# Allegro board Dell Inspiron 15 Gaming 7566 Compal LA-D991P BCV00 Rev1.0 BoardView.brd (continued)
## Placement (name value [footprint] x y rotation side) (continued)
PR810  0_0402_5%  [R0402_0OHM]  223.45 40.33 270 bottom
PR900  10K_0402_5%  [R_0402]  144.36 110.99 180 bottom
PR901  2.2_0603_5%  [R_0603]  143.37 114.53 90 bottom
PR902  30.1K_0402_1%  [R_0402]  144.36 110.1 180 bottom
PR903  0_0402_5%  [R0402_0OHM]  141.95 109.08 180 bottom
PR904  4.7_1206_5%  [R_1206]  144.35 124.32 180 top
PR905  470K_0402_1%  [R_0402]  138.06 110.91 90 bottom
PR906  9.31K_0402_1%  [R_0402]  140.17 109.08 180 bottom
PR907  10K_0402_1%  [R_0402]  140.17 110.1 180 bottom
PR908  0_0402_5%  [R0402_0OHM]  146.77 110.99 180 bottom
PR1000  0_0402_5%  [R0402_0OHM]  178.83 59.88 270 bottom
PR1001  10K_0402_1%  [R_0402]  177.81 59.88 270 bottom
PR1002  19.6K_0402_1%  [R_0402]  179.92 55.69 90 top
PR1003  2.2_0603_5%  [R_0603]  174 58.98 90 bottom
PR1004  2K_0402_1%  [R_0402]  180.81 57.52 180 top
PR1005  20K_0402_1%  [R_0402]  179.71 59.88 270 bottom
PR1006  18.2K_0402_1%  [R_0402]  180.81 58.41 180 top
PR1007  47K_0402_1%  [R_0402]  175.14 58.97 90 bottom
PR1008  47K_0402_1%  [R_0402]  176.92 58.97 90 bottom
PR1009  10_1206_5%  [R_1206]  165.62 57.08 270 top
PR1010  20_0402_1%  [R_0402]  180.73 54.55 270 top
PR1011  510K_0402_1%  [R_0402]  179.84 53.63 90 top
PR1012  0_0402_5%  [R0402_0OHM]  180.93 54.47 180 bottom
PR1013  100_0402_1%  [R_0402]  181.82 53.53 180 bottom
PR1014  13.3K_0402_1%  [R_0402]  171 55.49 0 bottom
PR1015  2.2_0603_5%  [R_0603]  174.38 51.36 270 bottom
PR1016  2.2_0603_5%  [R_0603]  171.84 53.65 270 bottom
PR1017  0_0402_5%  [R0402_0OHM]  181.82 52.64 180 bottom
PR1019  100_0402_1%  [R_0402]  181.82 51.76 180 bottom
PR1021  10K_0402_1%  [R_0402]  177.94 54.49 270 top
PR1022  10_1206_5%  [R_1206]  146.89 58.03 180 top
PR1023  10K_0402_1%  [R_0402]  178.95 53.13 90 top
PR1024  10K_0402_1%  [R_0402]  179.59 49.95 90 bottom
PR1026  1_0402_5%  [R_0402]  175.9 50.61 270 bottom
PR1027  10K_0402_1%  [R_0402]  178.19 49.95 90 bottom
PR1028  2.2_0603_5%  [R_0603]  177.05 51.11 270 bottom
PR1029  0_0402_5%  [R0402_0OHM]  200.19 58.03 0 top
PR1030  2.2_0603_5%  [R_0603]  207.49 58.36 180 top
PR1031  2.2_0603_5%  [R_0603]  201.09 55.24 180 top
PR1032  10_1206_5%  [R_1206]  189.18 70.48 0 top
PR1100  12.1K_0402_1%  [R_0402]  65.54 83.1 90 bottom
PR1101  1_0402_5%  [R_0402]  72.78 80.64 90 bottom
PR1102  0_0402_5%  [R0402_0OHM]  73.67 80.69 90 bottom
PR1103  45.3_0402_1%  [R_0402]  69.57 80.67 90 bottom
PR1104  100_0402_1%  [R_0402]  70.88 80.69 90 bottom
PR1105  97.6K_0402_1%  [R_0402]  64.78 85 90 bottom
PR1106  10_0402_1%  [R_0402]  70.88 83.1 90 bottom
PR1107  0_0402_5%  [R0402_0OHM]  69.99 83.1 90 bottom
PR1108  49.9_0402_1%  [R_0402]  69.1 83.1 90 bottom
PR1109  100_0402_1%  [R_0402]  68.46 83.1 90 top
PR1110  27.4K_0402_1%  [R_0402]  65.73 85.03 270 top
PR1111  10.2K_0402_1%  [R_0402]  66.62 84.11 90 top
PR1112  1.91K_0402_1%  [R_0402]  68.21 83.1 90 bottom
PR1113  165K_0402_1%  [R_0402]  76.51 85.33 0 bottom
PR1114  16.9K_0402_1%  [R_0402]  76.72 84.14 270 bottom
PR1115  5.62K_0402_1%  [R_0402]  75.83 84.14 270 bottom
PR1116  110K_0402_1%  [R_0402]  74.94 84.14 270 bottom
PR1117  0_0402_5%  [R0402_0OHM]  67.57 83.1 90 top
PR1118  3.6K_0402_1%  [R_0402]  65.72 87.75 0 top
PR1119  2K_0402_1%  [R_0402]  65.72 88.76 0 bottom
PR1120  0_0402_5%  [R0402_0OHM]  67.32 83.1 90 bottom
PR1121  1.1K_0402_1%  [R_0402]  76.51 88 0 bottom
PR1122  1K_0402_1%  [R_0402]  66.56 86.91 90 bottom
PR1123  48.7K_0402_1%  [R_0402]  76.51 86.22 0 bottom
PR1124  1K_0402_1%  [R_0402]  78.37 87.1 90 bottom
PR1125  2.61K_0402_1%  [R_0402]  129.17 118.1 180 bottom
PR1126  11K_0402_1%  [R_0402]  79.44 86.35 0 bottom
PR1127  2.94K_0402_1%  [R_0402]  64.7 87.81 0 bottom
PR1128  1K_0402_1%  [R_0402]  80.72 91.1 90 bottom
PR1129  2.67K_0402_1%  [R_0402]  80.71 90.16 0 bottom
PR1130  2.61K_0402_1%  [R_0402]  86.88 121.35 270 bottom
PR1131  11K_0402_1%  [R_0402]  63.43 91.43 0 bottom
PR1132  1K_0402_1%  [R_0402]  65.73 90.49 270 top
PR1133  4.42K_0402_1%  [R_0402]  78.55 92.57 0 bottom
PR1134  2K_0402_1%  [R_0402]  76.77 90.67 0 bottom
PR1135  115K_0402_1%  [R_0402]  77.61 91.73 90 bottom
PR1136  432_0402_1%  [R_0402]  66.62 90.49 270 top
PR1137  374_0402_1%  [R_0402]  76.6 95.75 180 bottom
PR1138  11K_0402_1%  [R_0402]  74.81 96.69 90 bottom
PR1139  1K_0402_1%  [R_0402]  76.34 97.6 270 bottom
PR1140  2.61K_0402_1%  [R_0402]  118.88 114.49 270 bottom
PR1141  10.2K_0402_1%  [R_0402]  68.84 95.7 270 bottom
PR1142  1K_0402_1%  [R_0402]  70.62 96.94 90 top
PR1143  90.9K_0402_1%  [R_0402]  67.07 94.78 90 bottom
PR1144  27.4K_0402_1%  [R_0402]  68.84 96.69 90 bottom
PR1145  2K_0402_1%  [R_0402]  70.62 94.78 90 bottom
PR1146  2.43K_0402_1%  [R_0402]  70.61 95.62 0 top
PR1147  4.87K_0402_1%  [R_0402]  69.73 94.78 90 bottom
PR1400  1_0402_5%  [R_0402]  121.04 129.48 270 top
PR1401  0_0402_5%  [R0402_0OHM]  121.42 132.02 270 bottom
PR1402  1_0402_5%  [R_0402]  123.2 132.02 270 bottom
PR1403  10K_0402_1%  [R_0402]  120.98 129.73 270 bottom
PR1404  0_0402_5%  [R0402_0OHM]  122.31 132.02 270 bottom
PR1405  4.7_0603_1%  [R_0603]  126.5 132.26 270 bottom
PR1406  10_1206_5%  [R_1206]  124.7 121.25 0 top
PR1407  0_0402_5%  [R0402_0OHM-NPM]  123.77 120.14 270 bottom
PR1408  0_0402_5%  [R0402_0OHM-NPM]  123.77 115.93 90 bottom
PR1409  100K_0402_1%  [R_0402]  79.21 101.21 180 bottom
PR1410  3.65K_0603_1%  [R_0603]  79.7 102.35 180 bottom
PR1411  2.2_0402_1%  [R_0402]  75.65 102.1 180 bottom
PR1412  100K_0402_1%  [R_0402]  74.74 101.08 0 bottom
PR1413  100K_0402_1%  [R_0402]  75.65 100.07 180 bottom
PR1414  1_0402_5%  [R_0402]  110.88 129.73 270 top
PR1415  0_0402_5%  [R0402_0OHM]  111.01 132.02 270 bottom
PR1416  1_0402_5%  [R_0402]  112.79 132.02 270 bottom
PR1417  0_0402_5%  [R0402_0OHM]  111.9 132.02 270 bottom
PR1418  10K_0402_1%  [R_0402]  110.82 129.73 270 bottom
PR1419  4.7_0603_1%  [R_0603]  116.09 132.26 270 bottom
PR1420  10_1206_5%  [R_1206]  113.99 121.28 0 top
PR1421  0_0402_5%  [R0402_0OHM-NPM]  114.88 120.21 270 bottom
PR1422  0_0402_5%  [R0402_0OHM-NPM]  114.88 115.99 90 bottom
PR1423  100K_0402_1%  [R_0402]  77.23 103.06 270 bottom
PR1424  3.65K_0603_1%  [R_0603]  77.04 104.26 180 bottom
PR1425  2.2_0402_1%  [R_0402]  73.37 102.1 180 bottom
PR1426  100K_0402_1%  [R_0402]  73.37 101.08 180 bottom
PR1427  100K_0402_1%  [R_0402]  73.37 100.07 180 bottom
PR1428  1_0402_5%  [R_0402]  100.97 129.61 270 top
PR1429  0_0402_5%  [R0402_0OHM]  101.36 131.89 270 bottom
PR1430  1_0402_5%  [R_0402]  103.13 131.89 270 bottom
PR1431  0_0402_5%  [R0402_0OHM]  102.24 131.89 270 bottom
PR1432  10K_0402_1%  [R_0402]  100.91 129.61 270 bottom
PR1433  4.7_0603_1%  [R_0603]  106.44 132.13 270 bottom
PR1434  10_1206_5%  [R_1206]  104.09 121.15 0 top
PR1435  0_0402_5%  [R0402_0OHM-NPM]  105.23 119.98 270 bottom
PR1436  0_0402_5%  [R0402_0OHM-NPM]  105.23 115.89 90 bottom
PR1437  100K_0402_1%  [R_0402]  72.45 104.38 0 bottom
PR1438  3.65K_0603_1%  [R_0603]  74.11 106.04 0 bottom
PR1439  2.2_0402_1%  [R_0402]  70.95 102.1 180 bottom
PR1440  100K_0402_1%  [R_0402]  70.95 100.07 180 bottom
PR1441  100K_0402_1%  [R_0402]  70.95 101.08 180 bottom
PR1500  1_0402_5%  [R_0402]  90.69 129.61 270 top
PR1501  0_0402_5%  [R0402_0OHM]  91.07 131.89 270 bottom
PR1502  1_0402_5%  [R_0402]  92.85 131.89 270 bottom
PR1503  0_0402_5%  [R0402_0OHM]  91.96 131.89 270 bottom
PR1504  10K_0402_1%  [R_0402]  90.75 129.61 270 bottom
PR1505  4.7_0603_1%  [R_0603]  96.15 132.13 270 bottom
PR1506  0_0402_5%  [R0402_0OHM-NPM]  91.83 120.08 270 bottom
PR1507  0_0402_5%  [R0402_0OHM-NPM]  91.83 115.86 90 bottom
PR1508  4.7_1206_5%  [R_1206]  93.75 121.12 0 top
PR1509  3.65K_0603_1%  [R_0603]  65.35 102.23 180 bottom
PR1510  100K_0402_1%  [R_0402]  64.86 101.08 180 bottom
PR1511  2.2_0402_1%  [R_0402]  65.87 103.37 180 bottom
PR1512  1_0402_5%  [R_0402]  71.51 106.97 90 bottom
PR1513  0_0402_5%  [R0402_0OHM]  67.37 108.55 0 bottom
PR1514  1_0402_5%  [R_0402]  67.37 110.35 0 bottom
PR1515  0_0402_5%  [R0402_0OHM]  67.37 109.46 0 bottom
PR1516  10K_0402_1%  [R_0402]  70.62 106.97 90 bottom
PR1517  4.7_0603_1%  [R_0603]  67.13 113.66 0 bottom
PR1518  4.7_1206_5%  [R_1206]  76.93 115.79 0 top
PR1519  0_0402_5%  [R0402_0OHM-NPM]  80.07 116.96 0 bottom
PR1520  0_0402_5%  [R0402_0OHM-NPM]  84.29 116.96 180 bottom
PR1521  3.65K_0603_1%  [R_0603]  66.49 106.54 180 bottom
PR1522  100K_0402_1%  [R_0402]  66.61 105.27 0 bottom
PR1523  2.2_0402_1%  [R_0402]  65.87 104.38 180 bottom
PR1524  4.7_1206_5%  [R_1206]  133.3 120.39 0 top
PR1525  100K_0402_1%  [R_0402]  65.87 103.37 180 top
PR1526  100K_0402_1%  [R_0402]  65.87 104.38 180 top
PR1527  1_0603_5%  [R_0603]  135.26 130.42 270 bottom
PR1528  3.65K_0603_1%  [R_0603]  132.79 117.21 180 top
PR1529  0_0402_5%  [R0402_0OHM]  132.55 116.07 180 top
PR1530  0_0402_5%  [R0402_0OHM]  131.84 130.17 270 bottom
PR1531  1_0402_5%  [R_0402]  132.85 130.17 270 top
PR1532  0_0402_5%  [R0402_0OHM]  130.69 127.37 90 bottom
PR1533  1_0402_5%  [R_0402]  130.82 127.83 270 top
PR1800  100K_0402_1%  [R_0402]  150.77 20.56 180 bottom
PR1801  0_0402_5%  [R0402_0OHM]  146.57 16.42 90 bottom
PR1803  21.5K_0402_1%  [R_0402]  146.11 26.72 0 bottom
PR1804  10K_0402_1%  [R_0402]  147.96 26.75 270 bottom
PR1805  0.01_0603_1%  [R_0603]  144.79 27.17 180 bottom
PT1400  PAD~D  [TPC12]  121.04 125.09 90 bottom
PT1401  PAD~D  [TPC12]  110.88 125.09 90 bottom
PT1402  PAD~D  [TPC12]  100.97 125.09 90 bottom
PT1500  PAD~D  [TPC12]  89.67 125.09 90 bottom
PT1501  PAD~D  [TPC12]  73.49 108.02 180 bottom
PT1503  PAD~D  [TPC12]  130.74 124.37 180 bottom
PU300  BQ24780SRUYR_QFN28_4X4  [BQ24780RUYR_WQFN28_4X4-S]  27.82 36.14 0 bottom
PU400  TPS51285BRUKR_QFN20_3X3  [TPS51285BRUKR_QFN20_3X3-S]  53.82 22.36 270 bottom
PU500  SY8210AQVC_QFN19_4X3  [SY8210AQVC_QFN19_4X3-S]  99.35 12.91 0 bottom
PU600  SY8286RAC_QFN20_3X3  [SY8286RAC_QFN20_3X3-S]  249.55 17.16 270 bottom
PU700  SY8286RAC_QFN20_3X3  [SY8286RAC_QFN20_3X3-S]  68.4 69.04 270 top
PU800  SY8286RAC_QFN20_3X3  [SY8286RAC_QFN20_3X3-S]  222.26 45.2 270 bottom
PU900  TPS51212DSCR_SON10_3X3  [TPS51212DSCR_SON10_3X3-S]  141.68 111.56 180 bottom
PU1000  RT8813AGQW_WQFN24_4X4  [RT8813AGQW_WQFN24_4X4-S]  174.76 56.89 0 bottom
PU1001  RT9610BZQW_WDFN8_2X2~D  [RT9610BZQW_WDFN8_2X2]  202.62 57.1 270 top
PU1100  ISL95829HRTZ-T_TQFN48_6X6  [ISL95855HRTZTS27_TQFN48_6X6-S]  68.72 87.37 0 bottom
PU1400  SIC632CDT1GE3_POWERPAK31_5X5  [SIC632CDT1GE_POWERPAKMLP31-28-S]  123.16 129.18 270 bottom
PU1401  SIC632CDT1GE3_POWERPAK31_5X5  [SIC632CDT1GE_POWERPAKMLP31-28-S]  113 129.18 270 bottom
PU1402  SIC632CDT1GE3_POWERPAK31_5X5  [SIC632CDT1GE_POWERPAKMLP31-28-S]  103.1 129.05 270 bottom
PU1500  SIC632CDT1GE3_POWERPAK31_5X5  [SIC632CDT1GE_POWERPAKMLP31-28-S]  92.81 129.05 270 bottom
PU1501  SIC632CDT1GE3_POWERPAK31_5X5  [SIC632CDT1GE_POWERPAKMLP31-28-S]  70.11 110.32 0 bottom
PU1503  SIC531CDT1GE3_POWERPAK22_4X3  [SIC531CDT1GE3_POWERPAK22_4X3-S]  132.85 127.24 270 bottom
PU1800  -  [RT9059GSP_SO8]  147.5 18.98 180 bottom
Q12  L2N7002LT1G_SOT23-3  [2N7002K_SOT23-3]  58.94 31.61 180 top
Q13  L2N7002LT1G_SOT23-3  [2N7002K_SOT23-3]  244.36 32.02 180 top
QA1  -  [L2N7002WT1G_SC-70-3]  257.44 26.22 0 bottom
QA2  SI3457BDV-T1-E3_TSOP6~D  [SI3457BDV-T1-E3_TSOP6]  254.97 28.17 270 bottom
QE3  -  [L2N7002WT1G_SC-70-3]  213.44 32.5 90 top
QE4  -  [DMG2301U-7_SOT23-3]  210.83 34.31 180 top
QE5  -  [L2N7002WT1G_SC-70-3]  119.12 15.41 270 top
QE13  -  [L2N7002WT1G_SC-70-3]  135.45 17.26 270 top
QE19  -  [DMN65D8LDW-7_SOT363-6]  148.78 16.35 90 bottom
QE20  -  [DMN65D8LDW-7_SOT363-6]  12.95 17.83 0 bottom
QE21  -  [DMN65D8LDW-7_SOT363-6]  15.74 17.83 0 bottom
QE23  -  [DMN65D8LDW-7_SOT363-6]  16.15 18.98 180 bottom
QE24  -  [DMN65D8LDW-7_SOT363-6]  288.56 60.51 270 bottom
QH4  -  [DMN65D8LDW-7_SOT363-6]  152.47 21.37 90 top
QH5  -  [DMN65D8LDW-7_SOT363-6]  152.17 23.81 180 bottom
QT1  MMBT3904WH_SOT323-3  [MMST3904-7-F_SOT323-3]  149.55 79.87 90 top
QT2  -  [DMN65D8LDW-7_SOT363-6]  52.4 47.35 90 bottom
QT3  MMBT3904WH_SOT323-3  [MMST3904-7-F_SOT323-3]  215.93 14.81 270 bottom
QV1  -  [DMN65D8LDW-7_SOT363-6]  149.17 73.67 270 bottom
QV2  -  [L2N7002WT1G_SC-70-3]  66.81 23.93 180 top
QV3  -  [DMN65D8LDW-7_SOT363-6]  146.93 74.22 0 top
QV11  SI3457BDV-T1-E3_TSOP6~D  [SI3457BDV-T1-E3_TSOP6]  62.38 21 0 top
QV20  -  [L2N7002WT1G_SC-70-3]  170.89 126.86 90 top
QV21  -  [L2N7002WT1G_SC-70-3]  204.16 92.83 270 top
QV85  -  [DMG2301U-7_SOT23-3]  152.53 80.28 180 top
QV88  -  [L2N7002WT1G_SC-70-3]  150.5 76.89 0 bottom
QZ6  -  [DMN65D8LDW-7_SOT363-6]  205.86 73.46 0 top
QZ7  -  [DMN65D8LDW-7_SOT363-6]  156.81 78.85 180 top
QZ8  -  [L2N7002WT1G_SC-70-3]  150.12 107.37 0 top
QZ9  -  [DMG2301U-7_SOT23-3]  210.98 47.79 270 bottom
RA1  0_0402_5%  [R0402_0OHM]  286.2 30.23 270 bottom
RA2  10K_0402_5%  [R_0402]  290.05 38.37 180 top
RA3  0_0603_5%  [R0603_0OHM]  287.89 30.24 90 top
RA5  0_0402_5%  [R0402_0OHM]  274.13 18.41 0 top
RA7  0_0805_5%  [R0805_0OHM]  274 31.42 0 bottom
RA8  0_0603_5%  [R0603_0OHM]  290.73 22.99 45 top
RA9  0_0402_5%  [R0402_0OHM]  279.01 21.79 135 bottom
RA10  0_0805_5%  [R0805_0OHM]  274 33.14 0 bottom
RA11  100K_0402_5%  [R_0402]  288.07 21.53 180 top
RA12  0_0402_5%  [R0402_0OHM]  291.47 14.29 270 bottom
RA13  0_0402_5%  [R0402_0OHM]  292.16 22.22 0 top
RA14  0_0402_5%  [R0402_0OHM]  284.19 23.8 180 bottom
RA15  0_0402_5%  [R0402_0OHM]  294.98 11.8 180 top
RA16  0_0805_5%  [R0805_0OHM]  278.1 18.21 270 bottom
RA17  0_0402_5%  [R_0402]  281.14 18.35 270 top
RA18  0_0402_5%  [R0402_0OHM]  282.03 18.35 270 top
RA19  0_0402_5%  [R0402_0OHM]  279.41 20.13 270 top
RA22  200K_0402_5%  [R_0402]  278.46 19.18 270 top
RA23  100K_0402_5%  [R_0402]  275.5 28.69 0 top
RA24  100K_0402_5%  [R_0402]  275.9 18.41 0 top
RA27  0_0402_5%  [R0402_0OHM]  272.22 27.23 0 top
RA28  22_0402_5%  [R_0402]  272.22 26.34 0 top
RA29  0_0402_5%  [R0402_0OHM]  274.63 25.9 0 bottom
RA30  1K_0402_5%  [R_0402]  279.61 15.66 90 top
RA31  0_0402_5%  [R0402_0OHM]  276.29 24.12 0 bottom
RA32  33_0402_5%  [R_0402]  274.51 23.74 0 top
RA33  10K_0402_5%  [R_0402]  280.5 16.58 270 top
RA35  4.7_0402_5%  [R_0402]  273.62 23.99 0 bottom
RA36  10_0201_5%  [R_0201]  270.46 23.83 90 top
RA37  10_0201_5%  [R_0201]  273.25 23.95 90 top
RA42  2.2K_0402_5%  [R_0402]  287.49 20.06 180 bottom
RA43  2.2K_0402_5%  [R_0402]  288.99 20.06 0 bottom
RA44  10_0402_1%  [R_0402]  296.48 13.2 0 top
RA46  4.7K_0402_5%  [R_0402]  296.48 12.31 0 top
RA48  1K_0402_5%  [R_0402]  296.48 14.09 0 top
RA49  10_0402_1%  [R_0402]  292.57 15.36 180 top
RA51  1K_0402_5%  [R_0402]  292.57 14.47 180 top
RA53  4.7K_0402_5%  [R_0402]  290.15 17.19 270 top
RA54  10K_0402_5%  [R_0402]  292.57 17.16 180 top
RA55  10K_0402_5%  [R_0402]  296.48 15.89 0 top
RA56  0_0402_5%  [R0402_0OHM]  291.6 15.79 90 bottom
RA57  10_0402_5%  [R_0402]  257.95 16.83 270 bottom
RA58  10_0402_5%  [R_0402]  269.12 16.68 90 bottom
RA60  0_0402_5%  [R_0402]  269.02 22.34 180 bottom
RA61  0_0402_5%  [R_0402]  269.02 23.21 180 bottom
RA62  10K_0402_5%  [R_0402]  268.28 21.45 0 bottom
RA63  10K_0402_5%  [R_0402]  266.33 23.94 270 bottom
RA64  10K_0402_5%  [R_0402]  268.11 24.09 0 bottom
RA65  45.3K_0402_1%  [R_0402]  261.88 23.94 270 bottom
RA66  0_0402_5%  [R_0402]  265.44 23.03 90 bottom
RA67  0_0402_5%  [R0402_0OHM]  262.77 23.03 90 bottom
RA70  100K_0402_5%  [R_0402]  276.49 26.96 90 bottom
RA71  1K_0402_1%  [R_0402]  284.52 17.44 90 top
RA72  1.2K_0201_1%  [R_0201]  283.63 18.28 270 top
RA73  665_0402_1%  [R_0402]  257.92 23.64 270 bottom
RA74  100K_0402_5%  [R_0402]  257.85 20.89 0 bottom
RA75  0_0805_5%  [R_0805]  270.52 20.4 270 bottom
RA76  0_0805_5%  [R0805_0OHM]  268.61 20.4 270 bottom
RA79  100K_0402_5%  [R_0402]  255.84 24.63 0 bottom
RA80  1M_0402_5%  [R_0402]  253.3 23.36 0 bottom
RC11  1K_0402_5%  [R_0402]  154.51 16.83 270 bottom
RD7  10K_0402_5%  [R_0402]  217.56 27.88 270 bottom
RD8  10K_0402_5%  [R_0402]  217.58 23.61 0 bottom
RD9  0_0402_5%  [R_0402]  217.56 20.36 90 bottom
RD10  10K_0402_5%  [R_0402]  205.11 19.88 270 bottom
RD31  0_0402_5%  [R0402_0OHM]  96.96 17.49 270 bottom
RD35  470_0402_1%  [R_0402]  97.85 17.49 270 bottom
RD58  0_0402_5%  [R0402_0OHM]  204.23 19.88 270 bottom
RD59  0_0402_5%  [R0402_0OHM]  217.56 25.75 270 bottom
RD62  0_0402_5%  [R_0402]  194 17.08 270 top
RE1  100K_0402_5%  [R_0402]  214.13 34.33 90 top
RE2  240_0402_1%  [R_0402]  209.86 36.19 0 top
RE3  47K_0402_5%  [R_0402]  120.33 16.25 270 top
RE4  100K_0402_1%  [R_0402]  121.22 15.33 90 top
RE7  2.4K_0402_5%  [R_0402]  149.81 15.05 270 bottom
RE9  2.4K_0402_5%  [R_0402]  149.86 19.68 0 bottom
RE10  10_0402_5%  [R_0402]  228.76 12.77 0 top
RE12  0_0603_5%  [R0603_0OHM]  239.98 20.06 180 top
RE13  22.1K_0402_1%  [R_0402]  230.58 28.74 90 bottom
RE14  100K_0402_1%  [R_0402]  229.69 28.74 90 bottom
RE15  0_0603_5%  [R0603_0OHM]  228.67 17.07 270 bottom
RE16  0_0603_5%  [R0603_0OHM]  221.94 34.66 0 bottom
RE17  43_0402_1%  [R_0402]  238.44 29.45 0 top
RE20  1K_0402_5%  [R_0402]  225.18 27.24 270 bottom
RE21  1K_0402_5%  [R_0402]  238.44 25.52 0 top
RE22  100K_0402_5%  [R_0402]  223.78 28.74 90 bottom
RE23  10K_0402_5%  [R_0402]  232.88 19.93 180 bottom
RE24  4.7K_0402_5%  [R_0402]  235.39 23.1 0 bottom
RE25  100K_0402_5%  [R_0402]  241.77 25.77 180 top
RE27  100K_0402_5%  [R_0402]  235.39 26.66 0 bottom
RE28  10K_0402_5%  [R_0402]  226.07 29.66 270 bottom
RE29  100K_0402_5%  [R_0402]  217.41 27.07 180 top
RE30  100K_0402_5%  [R_0402]  236.31 18.79 180 bottom
RE31  100K_0402_5%  [R_0402]  222.51 32.07 270 bottom
RE33  100K_0402_5%  [R_0402]  232.6 24.76 0 bottom
RE34  10K_0402_1%  [R_0402]  222.5 20.95 0 bottom
RE35  10K_0402_1%  [R_0402]  223.42 21.83 180 bottom
RE36  300_0402_5%  [R_0402]  232.61 27.5 270 bottom
RE38  100K_0402_5%  [R_0402]  232.6 23.87 0 bottom
RE39  100K_0402_5%  [R_0402]  217.41 29.4 180 top
RE40  15_0402_1%  [R_0402]  216.21 16.12 0 top
RE41  15_0402_1%  [R_0402]  216.21 18.79 0 top
RE42  15_0402_1%  [R_0402]  216.21 17.9 0 top
RE43  4.7K_0402_5%  [R_0402]  223.07 27.17 0 bottom
RE44  4.7K_0402_5%  [R_0402]  223.07 26.28 0 bottom
RE45  2.2K_0402_5%  [R_0402]  223.07 25.26 0 bottom
RE46  2.2K_0402_5%  [R_0402]  223.07 24.25 0 bottom
RE47  10K_0402_5%  [R_0402]  221.75 29.66 270 bottom
RE52  100K_0402_5%  [R_0402]  223.4 31.16 90 bottom
RE53  100K_0402_5%  [R_0402]  222.62 13.35 270 top
RE55  4.7K_0402_5%  [R_0402]  235.39 23.99 0 bottom
RE57  0_0402_5%  [R0402_0OHM]  238.44 27.55 0 top
RE58  0_0402_5%  [R0402_0OHM]  225.18 29.66 270 bottom
RE59  0_0402_5%  [R0402_0OHM]  216.21 19.68 0 top
RE60  49.9_0402_1%  [R_0402]  245.45 34.28 180 bottom
RE61  0_0402_5%  [R0402_0OHM]  221.73 13.35 270 top
RE62  0_0402_5%  [R0402_0OHM]  225.49 14.09 0 bottom
RE63  10K_0402_5%  [R_0402]  254.01 31.41 90 bottom
RE64  10K_0402_5%  [R_0402]  255.79 31.41 90 bottom
RE65  100K_0402_5%  [R_0402]  254.9 31.41 90 bottom
RE66  0_0402_5%  [R_0402]  223.61 34.53 180 top
RE67  0_0603_5%  [R0603_0OHM]  227.72 25.96 90 bottom
RE68  0_0402_5%  [R_0402]  241.77 26.66 180 top
RE71  15_0402_1%  [R_0402]  171.13 10.79 0 bottom
RE73  0_0402_5%  [R0402_0OHM]  233.56 25.82 90 bottom
RE81  100K_0402_5%  [R_0402]  52.08 31.94 270 top
RE82  10K_0402_5%  [R_0402]  55.76 29.71 180 top
RE83  100K_0402_5%  [R_0402]  51.19 31.94 270 top
RE84  10K_0402_5%  [R_0402]  243.57 36.95 0 top
RE87  100K_0402_5%  [R_0402]  132.47 14.93 270 top
RE93  0_0603_5%  [R0603_0OHM]  135.01 15.42 270 top
RE100  10K_0402_5%  [R_0402]  56.52 31.16 90 top
RE101  10K_0402_5%  [R_0402]  243.57 34.41 0 top
RE104  0_0603_5%  [R0603_0OHM]  55.25 30.66 90 top
RE105  0_0603_5%  [R0603_0OHM]  243.07 35.68 0 top
RE106  0_0402_5%  [R0402_0OHM]  220.79 34.53 0 top
RE108  10K_0402_5%  [R_0402]  216.21 17.01 0 top
RE109  0_0402_5%  [R0402_0OHM]  250.07 32.32 270 bottom
RE110  0_0402_5%  [R0402_0OHM]  251.09 32.32 270 bottom
RE111  0_0402_5%  [R0402_0OHM]  252.1 32.32 270 bottom
RE112  0_0402_5%  [R0402_0OHM]  253.12 32.32 270 bottom
RE113  100K_0402_5%  [R_0402]  230.39 34.46 90 top
RE114  100K_0402_5%  [R_0402]  239.35 28.44 180 top
RE116  0_0402_5%  [R0402_0OHM]  236.92 29.58 0 bottom
RE118  10K_0402_5%  [R_0402]  256.75 33.39 180 bottom
RE119  100K_0402_5%  [R_0402]  238.39 19.55 90 bottom
RE120  100K_0402_5%  [R_0402]  216.42 32.96 270 top
RE121  10K_0402_5%  [R_0402]  59.95 26.79 90 top
RE122  10K_0402_5%  [R_0402]  243.77 28.06 0 top
RE123  100K_0402_5%  [R_0402]  141.42 16.42 90 top
RE124  100K_0402_1%  [R_0402]  228.36 34.74 270 bottom
RE125  10K_0402_1%  [R_0402]  226.58 34.74 270 bottom
RE126  15_0402_1%  [R_0402]  171.26 8.37 0 bottom
RE127  15_0402_1%  [R_0402]  185.23 11.14 180 bottom
RE128  15_0402_1%  [R_0402]  171.26 7.36 0 bottom
RE129  15_0402_1%  [R_0402]  184.39 9.34 90 bottom
RH1  0_0402_5%  [R_0402]  168.79 14.04 270 bottom
RH9  0_0402_5%  [R0402_0OHM]  179.79 26.79 180 top
RH10  10K_0402_5%  [R_0402]  159.39 18.33 90 top
RH11  0_0402_5%  [R0402_0OHM]  173.8 14.21 0 bottom
RH13  100K_0402_5%  [R_0402]  178.52 25.9 180 top
RH14  5.1K_0402_1%  [R_0402]  153.86 25.52 0 top
RH15  5.1K_0402_1%  [R_0402]  153.86 24.63 0 top
RH16  22_0402_5%  [R_0402]  184.81 25.31 0 top
RH17  1K_0402_5%  [R_0402]  171.08 16.32 270 bottom
RH18  1K_0402_5%  [R_0402]  186.42 15.48 180 top
RH20  0_0402_5%  [R_0402]  160.81 35.72 0 top
RH21  1K_0402_5%  [R_0402]  148.52 21.33 0 top
RH22  1K_0402_5%  [R_0402]  154.52 22.72 180 top
RH23  1K_0402_5%  [R_0402]  158.71 24.29 180 top
RH24  24.9_0402_1%  [R_0402]  123.92 68.71 0 bottom
RH25  1K_0402_5%  [R_0402]  158.71 25.64 180 top
RH26  1K_0402_5%  [R_0402]  148.52 22.72 0 top
RH27  1K_0402_5%  [R_0402]  154.52 21.33 180 top
RH28  0_0402_5%  [R0402_0OHM]  105.78 105.23 180 bottom
RH29  100_0402_1%  [R_0402]  106.7 105.23 0 bottom
RH30  24.9_0402_1%  [R_0402]  127.14 99.99 90 top
RH31  0_0402_5%  [R0402_0OHM]  117.52 103.22 90 bottom
RH32  0_0402_5%  [R0402_0OHM]  105.78 104.27 180 bottom
RH33  100_0402_1%  [R_0402]  106.7 104.27 0 bottom
RH34  0_0402_5%  [R0402_0OHM]  114.24 82.11 270 top
RH38  0_0402_5%  [R0402_0OHM]  84.39 92.19 0 bottom
RH41  100_0402_1%  [R_0402]  116.63 103.22 90 bottom
RH45  0_0402_5%  [R0402_0OHM]  69.91 44.01 0 top
RH46  0_0402_5%  [R0402_0OHM]  111.55 22.01 270 top
RH47  0_0402_5%  [R0402_0OHM]  186.42 16.37 180 top
RH56  51_0402_5%  [R_0402]  84.9 95.88 0 top
RH57  49.9_0402_1%  [R_0402]  84.39 88.64 0 bottom
RH58  49.9_0402_1%  [R_0402]  84.39 90.41 0 bottom
RH59  49.9_0402_1%  [R_0402]  85.3 89.53 180 bottom
RH60  51_0402_5%  [R_0402]  82.1 95.49 0 bottom
RH61  51_0402_5%  [R_0402]  84.39 91.3 0 bottom
RH62  499_0402_1%  [R_0402]  153.22 25.01 90 bottom
RH63  499_0402_1%  [R_0402]  156.14 20.31 0 top
RH64  4.7K_0402_5%  [R_0402]  159.65 24.25 0 top
RH65  150K_0402_5%  [R_0402]  165.09 28.94 270 top
RH66  4.7K_0402_5%  [R_0402]  156.14 21.2 0 top
RH67  1M_0402_5%  [R_0402]  169.68 18.99 270 top
RH68  10K_0402_5%  [R_0402]  154.74 33.31 180 top
RH69  10K_0402_5%  [R_0402]  154.85 31.11 180 bottom
RH70  10M_0402_5%  [R_0402]  175.47 19.04 180 bottom
RH71  2.7K_0402_1%  [R_0402]  178.83 43.63 270 top
RH72  1M_0402_5%  [R_0402]  182 45.02 270 bottom
RH74  4.7K_0402_5%  [R_0402]  160.08 14.72 0 bottom
RH77  100K_0402_5%  [R_0402]  169.67 13.52 0 bottom
RH79  10K_0402_5%  [R_0402]  154.52 37.33 180 bottom
RH80  10K_0402_5%  [R_0402]  151.98 31.49 180 top
RH81  8.2K_0402_5%  [R_0402]  170.19 16.14 270 bottom
RH82  4.7K_0402_5%  [R_0402]  165.49 18.2 90 top
RH83  20K_0402_5%  [R_0402]  177.05 18.76 90 top
RH84  20K_0402_5%  [R_0402]  175.27 18.76 90 top
RH85  8.2K_0402_5%  [R_0402]  168.79 18.99 270 top
RH86  10K_0402_5%  [R_0402]  153.73 30.6 0 top
RH87  10K_0402_5%  [R_0402]  180.68 24.88 180 top
RH88  47K_0402_5%  [R_0402]  180.6 18.33 90 top
RH89  0_0402_5%  [R_0402]  154.74 35.21 180 top
RH90  10K_0402_5%  [R_0402]  171.46 18.86 270 bottom
RH91  10K_0402_5%  [R_0402]  153.98 28.9 0 bottom
RH92  4.7K_0402_5%  [R_0402]  164.6 18.46 90 top
RH93  220K_0402_5%  [R_0402]  80.49 81.83 0 bottom
RH94  10K_0402_5%  [R_0402]  188.52 27.97 180 top
RH95  51_0402_5%  [R_0402]  189.37 35.88 270 bottom
RH96  0_0402_5%  [R0402_0OHM]  182.97 19.04 180 bottom
RH97  51_0402_5%  [R_0402]  182 35.12 270 top
RH98  51_0402_5%  [R_0402]  182.89 35.12 270 top
RH100  51_0402_5%  [R_0402]  181.11 35.12 270 top
RH101  0_0402_5%  [R0402_0OHM]  161.86 14.72 0 bottom
RH102  0_0402_5%  [R_0402]  190.3 27.97 180 top
RH103  0_0402_5%  [R0402_0OHM]  192.08 24.42 180 top
RH104  22_0402_1%  [R_0402]  163.2 18.93 270 bottom
RH105  0_0402_5%  [R0402_0OHM]  191.16 25.43 0 top
RH106  0_0402_5%  [R0402_0OHM]  192.08 26.32 180 top
RH107  0_0402_5%  [R_0402]  115.9 81.24 90 top
RH108  100_0402_1%  [R_0402]  171 45.88 180 bottom
RH109  113_0402_1%  [R_0402]  178.88 29.86 0 top
RH110  10K_0402_5%  [R_0402]  154.74 32.42 180 top
RH111  10K_0402_5%  [R_0402]  180.68 23.99 180 top
RH112  1K_0402_5%  [R_0402]  175.05 33.24 180 top
RH113  1K_0402_5%  [R_0402]  182.56 34.92 180 bottom
RH114  0_0402_5%  [R0402_0OHM]  173.8 13.33 0 bottom
RH115  0_0402_5%  [R0402_0OHM]  84.9 94.1 0 top
RH118  0_0402_5%  [R0402_0OHM]  84.9 96.76 0 top
RH119  2.2K_0402_5%  [R_0402]  153.86 26.66 0 top
RH120  2.2K_0402_5%  [R_0402]  153.98 27.12 0 bottom
RH121  0_0603_5%  [R0603_0OHM]  171.84 12.25 90 bottom
RH122  0_0603_5%  [R0603_0OHM]  184.9 39.8 270 bottom
RH123  0_0603_5%  [R0603_0OHM]  180.35 28.82 180 top
RH124  0_0603_5%  [R0603_0OHM]  160.22 45.76 180 top
RH125  8.2K_0402_5%  [R_0402]  172.35 19.62 270 bottom
RH126  10K_0402_5%  [R_0402]  169.86 22.47 0 top
RH127  10K_0402_5%  [R_0402]  163.25 27.97 180 top
RH128  10K_0402_5%  [R_0402]  170.57 18.86 270 bottom
RH129  10K_0402_5%  [R_0402]  154.65 29.71 180 top
RH130  4.7K_0402_5%  [R_0402]  164.19 28.94 270 top
RH131  10K_0402_5%  [R_0402]  154.65 31.49 180 top
RH132  10K_0402_5%  [R_0402]  154.87 32.74 180 bottom
RH134  10K_0402_5%  [R_0402]  154.87 33.63 180 bottom
RH135  10K_0402_5%  [R_0402]  154.74 34.2 180 top
RH137  0_0603_5%  [R0603_0OHM]  169.49 15.87 180 top
RH138  13_0402_5%  [R_0402]  186.09 34.94 90 bottom
RH141  2.2K_0402_5%  [R_0402]  177.86 23.74 0 top
RH142  2.2K_0402_5%  [R_0402]  177.86 22.85 0 top
RH143  330K_0402_5%  [R_0402]  176.16 19.68 270 top
RH144  49.9_0402_1%  [R_0402]  84.9 94.99 0 top
RH145  20_0402_5%  [R_0402]  134.05 95.49 0 top
RH146  30_0402_5%  [R_0402]  187.33 35.88 270 bottom
RH147  30_0402_5%  [R_0402]  188.22 35.88 270 bottom
RH148  121_0402_1%  [R_0402]  123.92 69.6 0 bottom
RH149  75_0402_1%  [R_0402]  123.92 70.49 0 bottom
RH150  100_0402_1%  [R_0402]  121.71 69.51 0 bottom
RH151  100_0402_5%  [R_0402]  85.91 90.29 0 top
RH152  56.2_0402_1%  [R_0402]  84.97 90.21 90 top
RH153  220_0402_5%  [R_0402]  85.91 91.18 0 top
RH154  60.4_0402_1%  [R_0402]  131.66 76.44 180 top
RH155  20_0402_5%  [R_0402]  82.1 97.37 0 bottom
RH156  51_0402_5%  [R_0402]  82.1 93.46 0 bottom
RH158  499_0402_1%  [R_0402]  84.39 94.61 0 bottom
RH159  49.9K_0402_1%  [R_0402]  153.73 27.93 0 top
RH160  49.9K_0402_1%  [R_0402]  153.98 28.01 0 bottom
RH163  1K_0402_5%  [R_0402]  123.42 95.45 180 top
RH164  1K_0402_5%  [R_0402]  130.74 77.33 0 top
RH165  1K_0402_5%  [R_0402]  82.1 94.61 0 bottom
RH166  49.9_0402_1%  [R_0402]  84.39 93.34 0 bottom
RH167  30_0402_5%  [R_0402]  134.96 93.59 180 top
RH168  22_0402_5%  [R_0402]  170.57 18.99 270 top
RH179  10K_0402_5%  [R_0402]  167.01 18.99 270 top
RH180  100K_0402_5%  [R_0402]  189.01 24.42 0 top
RH181  10K_0402_5%  [R_0402]  172.09 16.32 270 bottom
RH183  1K_0402_5%  [R_0402]  89.16 90.87 270 top
RH184  1K_0402_5%  [R_0402]  88.27 90.87 270 top
RH185  1K_0402_5%  [R_0402]  85.3 85.97 180 bottom
RH186  1K_0402_5%  [R_0402]  85.3 84.95 180 bottom
RH187  1K_0402_5%  [R_0402]  85.3 86.86 180 bottom
RH188  1K_0402_5%  [R_0402]  85.3 87.75 180 bottom
RH189  30_0402_5%  [R_0402]  184.29 34.89 90 bottom
RH190  0_0402_5%  [R0402_0OHM]  82.1 98.24 0 bottom
RH191  620_0402_5%  [R_0402]  183.4 34.89 90 bottom
RH192  30_0402_5%  [R_0402]  134.96 94.48 180 top
RH193  8.2K_0402_5%  [R_0402]  182.05 20.06 0 bottom
RH196  0_0402_5%  [R_0402]  167.52 28.9 270 top
RH197  100_0402_1%  [R_0402]  107.62 106.3 180 bottom
RH198  0_0402_5%  [R0402_0OHM]  105.78 106.3 180 bottom
RH201  100_0402_1%  [R_0402]  119.3 103.22 90 bottom
RH202  0_0402_5%  [R0402_0OHM]  118.41 103.22 90 bottom
RH203  100_0402_1%  [R_0402]  107.62 102.81 180 bottom
RH204  0_0402_5%  [R0402_0OHM]  105.78 102.81 180 bottom
RH206  1K_0402_1%  [R_0402]  71.77 43.96 270 top
RH207  1K_0402_1%  [R_0402]  112.43 19.97 90 top
RH209  1K_0402_1%  [R_0402]  70.83 42.99 180 top
RH210  1K_0402_1%  [R_0402]  112.43 21.72 90 top
RH211  24.9_0402_1%  [R_0402]  70.85 45.84 180 top
RH212  24.9_0402_1%  [R_0402]  112.84 25.11 180 top
RH492  0_0402_5%  [R0402_0OHM]  183.78 34.2 90 top
RH493  0_0603_5%  [R_0603]  150.95 22.22 0 bottom
RH494  10K_0402_5%  [R_0402]  153.73 28.82 0 top
RH495  10K_0402_5%  [R_0402]  155.89 29.07 0 top
RH496  51_0402_5%  [R_0402]  83.07 91.48 90 bottom
RH497  51_0402_5%  [R_0402]  84.9 93.21 0 top
RH499  0_0402_5%  [R_0402]  189.93 23.54 180 top
RH500  10K_0402_5%  [R_0402]  167.9 18.99 270 top
RH502  0_0402_5%  [R_0402]  19.52 17.26 180 bottom
RH503  0_0402_5%  [R0402_0OHM]  181.49 18.33 90 top
RH504  100K_0402_5%  [R_0402]  13.6 20.01 270 bottom
RH505  100K_0402_5%  [R_0402]  15.5 22.93 270 bottom
RH506  100K_0402_5%  [R_0402]  285.71 59.76 90 bottom
RH507  22_0402_1%  [R_0402]  162.32 18.99 270 bottom
RH508  22_0402_1%  [R_0402]  164.09 18.93 270 bottom
RH509  22_0402_1%  [R_0402]  164.98 18.93 270 bottom
RH510  22_0402_1%  [R_0402]  165.87 19.05 270 bottom
RH513  0_0402_5%  [R0402_0OHM]  121.6 83.34 180 top
RH514  0_0402_5%  [R0402_0OHM]  121.6 84.22 180 top
RH515  100_0402_1%  [R_0402]  123.12 83.81 0 top
RH516  100_0402_1%  [R_0402]  123.12 82.92 0 top
RI9  100K_0402_5%  [R_0402]  282.36 32.73 0 top
RI10  100K_0402_5%  [R_0402]  277.78 34.15 0 top
RI30  100K_0402_5%  [R_0402]  277.76 35.91 0 top
RI37  0_0402_5%  [R0402_0OHM]  288.05 31.49 0 bottom
RI38  0_0402_5%  [R0402_0OHM]  288.05 32.5 0 bottom
RI39  0_0402_5%  [R0402_0OHM]  288.05 33.65 0 bottom
RI40  0_0402_5%  [R0402_0OHM]  288.05 34.66 0 bottom
RI41  0_0402_5%  [R0402_0OHM]  289.11 50.66 0 bottom
RI42  0_0402_5%  [R0402_0OHM]  289.11 51.68 0 bottom
RI43  0_0402_5%  [R0402_0OHM]  289.11 52.7 0 bottom
RI44  0_0402_5%  [R0402_0OHM]  289.11 53.71 0 bottom
RI45  22.1K_0402_1%  [R_0402]  281.01 39.06 180 top
RI49  22.1K_0402_1%  [R_0402]  281.01 40 180 top
RI51  1M_0402_5%  [R_0402]  277.78 35.04 0 top
RL1  0_0402_5%  [R_0402]  284.26 38.22 0 bottom
RL2  0_0402_5%  [R0402_0OHM]  286.14 39.79 90 bottom
RL19  75_0402_5%  [R_0402]  303.41 90.62 270 top
RL20  75_0402_5%  [R_0402]  300.36 90.62 270 top
RL27  100K_0402_5%  [R_0402]  278.76 47.49 180 bottom
RL30  15K_0402_1%  [R_0402]  286.01 38.17 270 bottom
RL31  2.49K_0402_1%  [R_0402]  280.1 47.49 0 bottom
RL33  1K_0402_5%  [R_0402]  286.9 37.25 90 bottom
RL39  75_0402_5%  [R_0402]  297.44 90.62 270 top
RL40  75_0402_5%  [R_0402]  294.52 90.62 270 top
RL41  100K_0402_5%  [R_0402]  279.42 51.87 180 bottom
RL42  1K_0402_5%  [R_0402]  285.63 41.6 270 top
RL43  0_0402_5%  [R0402_0OHM]  280.93 39.79 90 bottom
RM1  2.2K_0402_5%  [R_0402]  299.45 63.19 0 top
RM2  2.2K_0402_5%  [R_0402]  298.59 63.19 180 top
RM3  1K_0402_5%  [R_0402]  263.03 30.17 270 top
RM4  4.3K_0402_5%  [R_0402]  260.92 42.46 90 top
RM5  10K_0402_5%  [R_0402]  262.14 30.17 270 top
RM6  10K_0402_5%  [R_0402]  263.53 42.1 270 bottom
RM7  4.7K_0402_5%  [R_0402]  264.04 30.17 270 top
RM8  10K_0402_5%  [R_0402]  261.33 25.26 180 top
RM9  4.7K_0402_5%  [R_0402]  265.06 30.17 270 top
RM10  4.7K_0402_5%  [R_0402]  270.01 26.86 270 top
RM11  4.7K_0402_5%  [R_0402]  264.3 40.83 270 top
RM12  4.7K_0402_5%  [R_0402]  261.55 31.87 0 bottom
RM13  4.7K_0402_5%  [R_0402]  265.39 34.28 180 bottom
RM14  4.7K_0402_5%  [R_0402]  270.9 41.85 270 top
RM15  0_0603_5%  [R0603_0OHM]  270.39 44 90 top
RM16  4.7K_0402_5%  [R_0402]  270.9 41.85 270 bottom
RM17  4.7K_0402_5%  [R_0402]  270.01 40.93 90 bottom
RM18  4.7K_0402_5%  [R_0402]  270.01 40.93 90 top
RM19  0_0402_5%  [R0402_0OHM]  270.57 32.88 0 top
RM20  4.7K_0402_5%  [R_0402]  263.56 43.37 270 top
RM21  10K_0402_5%  [R_0402]  257.18 29.63 90 bottom
RM22  0_0603_5%  [R0603_0OHM]  204.42 25.01 180 top
RM23  10K_0402_5%  [R_0402]  262.68 43.37 270 top
RM24  10K_0402_5%  [R_0402]  261.81 42.46 90 top
RM25  68_0402_5%  [R_0402]  260.44 39.56 0 top
RM26  68_0402_5%  [R_0402]  260.51 41.57 0 top
RM27  0_0402_5%  [R0402_0OHM]  261.03 29.25 90 top
RN1  0_0402_5%  [R_0402]  195.15 35.09 90 bottom
RN2  0_0402_5%  [R_0402]  201.86 23.84 90 top
RN3  0_0402_5%  [R_0402]  195.01 28.69 0 top
RN4  100K_0402_5%  [R_0402]  195.01 29.58 0 top
RN5  0_0402_5%  [R0402_0OHM]  194.07 28.62 90 top
RP2  10K_0804_8P4R_5%  [RP_0804_8P4R]  169.42 17.58 90 bottom
RP3  10K_0804_8P4R_5%  [RP_0804_8P4R]  161.82 18.85 90 top
RP8  10K_0804_8P4R_5%  [RP_0804_8P4R]  154.38 36.24 180 bottom
RP15  33_0804_8P4R_5%  [RP_0804_8P4R]  180.97 15.67 90 bottom
RP22  10K_0804_8P4R_5%  [RP_0804_8P4R]  161.25 17.16 90 bottom
RP23  10K_0804_8P4R_5%  [RP_0804_8P4R]  158.46 17.16 90 bottom
RPE2  10K_0804_8P4R_5%  [RP_0804_8P4R]  233.19 34.85 90 top
RPE3  10K_0804_8P4R_5%  [RP_0804_8P4R]  229.77 32.32 270 bottom
RPE4  100K_0804_8P4R_5%  [RP_0804_8P4R]  215.88 25.47 0 top
RPE5  100K_0804_8P4R_5%  [RP_0804_8P4R]  224.1 11.91 90 top
RPE6  100K_0804_8P4R_5%  [RP_0804_8P4R]  235.27 20.32 0 bottom
RPE7  100K_0804_8P4R_5%  [RP_0804_8P4R]  239.98 22.61 180 top
RT1  7.87K_0402_1%  [R_0402]  108.98 83.96 180 top
RT3  10K_0402_5%  [R_0402]  57.08 46.47 0 bottom
RT4  10K_0402_5%  [R_0402]  55.38 47.79 90 bottom
RT5  10K_0402_5%  [R_0402]  51.32 48.2 270 bottom
RT6  0_0402_5%  [R_0402]  52.89 45.96 0 bottom
RT7  0_0402_5%  [R_0402]  53.81 49.77 180 bottom
RV27  100K_0402_5%~D  [R_0402]  172.77 73.78 0 bottom
RV34  10K_0402_5%  [R_0402]  151.21 75.68 180 bottom
RV37  10K_0402_5%  [R_0402]  161.88 76.32 180 top
RV39  10K_0402_5%  [R_0402]  148.01 80 0 bottom
RV40  0_0402_5%  [R0402_0OHM]  149.79 80 0 bottom
RV41  10K_0402_5%  [R_0402]  150.37 73.83 90 bottom
RV42  10K_0402_5%  [R_0402]  164.02 72.71 180 bottom
RV45  0_0402_5%  [R_0402]  162 82.32 180 top
RV47  200_0402_1%  [R_0402]  158.45 98.29 180 top
RV49  10K_0402_5%  [R_0402]  177.09 74.67 0 top
RV50  2.49K_0402_1%  [R_0402]  149.4 99.43 0 bottom
RV51  10K_0402_5%  [R_0402]  174.3 77.44 270 top
RV52  10M_0402_5%  [R_0402]  177.14 73.75 0 bottom
RV55  10K_0402_1%  [R_0402]  173.72 72.76 0 top
RV56  10K_0402_5%  [R_0402]  149.05 82.03 180 top
RV57  10K_0402_5%  [R_0402]  151.08 82.03 180 top
RV58  10K_0402_5%  [R_0402]  140.22 77.16 270 bottom
RV60  100K_0402_5%~D  [R_0402]  174.63 73.65 180 top
RV62  10K_0402_5%  [R_0402]  152.22 82.34 180 bottom
RV63  10K_0402_5%  [R_0402]  152.22 84.06 180 bottom
RV66  40.2K_0402_1%  [R_0402]  177.09 73.78 0 top
RV77  40.2_0402_1%  [R_0402]  175.44 101.57 270 top
RV78  40.2_0402_1%  [R_0402]  176.33 101.57 270 top
RV79  60.4_0402_1%  [R_0402]  178.62 92.45 90 top
RV95  10K_0402_5%  [R_0402]  162.21 106.38 0 top
RV96  10K_0402_5%  [R_0402]  181.43 88.45 315 top
RV98  10K_0402_5%  [R_0402]  163.99 104.75 0 top
RV99  10K_0402_5%  [R_0402]  182.5 89.16 0 top
RV104  10K_0402_5%  [R_0402]  180.73 71.67 90 bottom
RV107  10K_0402_5%  [R_0402]  163.12 105.46 180 top
RV108  10K_0402_5%  [R_0402]  166.34 103.55 315 top
RV110  10K_0402_5%  [R_0402]  182.35 90.07 180 top
RV111  10K_0402_5%  [R_0402]  182.7 87.22 225 top
RV116  1K_0402_1%  [R_0402]  174.32 125.94 90 top
RV117  1K_0402_1%  [R_0402]  167.14 126.34 90 top
RV118  1K_0402_1%  [R_0402]  181.21 127.76 180 top
RV119  1K_0402_1%  [R_0402]  160.01 124.9 0 top
RV120  121_0402_1%  [R_0402]  181.2 128.69 180 top
RV121  121_0402_1%  [R_0402]  160 125.82 0 top
RV123  80.6_0402_1%  [R_0402]  186.32 126.18 270 top
RV125  549_0402_1%  [R_0402]  171.6 129.69 0 top
RV126  931_0402_1%  [R_0402]  171.59 128.77 0 top
RV127  1.33K_0402_1%  [R_0402]  172.57 130.57 90 top
RV128  549_0402_1%  [R_0402]  169.9 129.66 180 top
RV129  931_0402_1%  [R_0402]  169.9 128.74 180 top
RV130  1.33K_0402_1%  [R_0402]  169.88 130.53 90 top
RV131  1K_0402_1%  [R_0402]  203.57 95.76 180 top
RV132  1K_0402_1%  [R_0402]  204.05 88.64 180 top
RV133  1K_0402_1%  [R_0402]  203.39 103.12 270 top
RV134  1K_0402_1%  [R_0402]  199.66 80.82 180 top
RV135  121_0402_1%  [R_0402]  204.33 103.12 270 top
RV136  121_0402_1%  [R_0402]  199.65 81.74 180 top
RV138  80.6_0402_1%  [R_0402]  205.45 107.69 180 top
RV140  549_0402_1%  [R_0402]  203.37 94.74 0 top
RV141  931_0402_1%  [R_0402]  205.24 93.83 90 top
RV142  1.33K_0402_1%  [R_0402]  206.15 94.74 0 top
RV143  549_0402_1%  [R_0402]  205.25 90.2 90 top
RV144  931_0402_1%  [R_0402]  205.25 92.87 270 top
RV145  1.33K_0402_1%  [R_0402]  206.19 91.95 0 top
RV146  49.9K_0402_1%  [R_0402]  183.52 74.36 270 top
RV147  34.8K_0402_1%  [R_0402]  188.22 74.36 270 top
RV148  10K_0402_1%  [R_0402]  187.33 74.36 270 top
RV149  15K_0402_1%  [R_0402]  189.1 74.36 270 top
RV150  20K_0402_1%  [R_0402]  184.41 74.36 270 top
RV152  49.9K_0402_1%  [R_0402]  182.63 73.45 90 top
RV153  34.8K_0402_1%  [R_0402]  188.22 76.65 270 top
RV154  4.99K_0402_1%  [R_0402]  187.33 76.65 270 top
RV155  4.99K_0402_1%  [R_0402]  189.1 76.65 270 top
RV156  20K_0402_1%  [R_0402]  184.41 76.65 270 top
RV157  4.99K_0402_1%  [R_0402]  185.42 74.36 270 top
RV158  4.99K_0402_1%  [R_0402]  186.44 74.36 270 top
RV159  4.99K_0402_1%  [R_0402]  189.99 74.36 270 top
RV160  15K_0402_1%  [R_0402]  185.42 76.65 270 top
RV161  4.99K_0402_1%  [R_0402]  186.44 76.65 270 top
RV162  4.99K_0402_1%  [R_0402]  189.99 76.65 270 top
RV175  80.6_0402_1%  [R_0402]  155.97 126.18 270 top
RV178  80.6_0402_1%  [R_0402]  204.94 76.72 180 top
RV187  10K_0402_5%  [R_0402]  143.22 78.6 180 bottom
RV191  1.8K_0402_5%  [R_0402]  160.51 73.57 180 bottom
RV192  1.8K_0402_5%  [R_0402]  160.51 71.92 180 bottom
RV208  0_0402_5%  [R_0402]  148.72 78.15 90 bottom
RV209  100K_0402_5%  [R_0402]  157.69 75.38 0 top
RV510  1.8K_0402_5%  [R_0402]  170.11 73.78 270 bottom
RV511  1.8K_0402_5%  [R_0402]  170.99 73.78 270 bottom
RV512  1.8K_0402_5%  [R_0402]  164.29 76.32 180 top
RV513  1.8K_0402_5%  [R_0402]  164.29 75.43 180 top
RV514  1.8K_0402_5%  [R_0402]  169.22 73.78 270 bottom
RV515  1.8K_0402_5%  [R_0402]  168.33 73.78 270 bottom
RV526  10K_0402_5%  [R_0402]  171.88 73.78 270 bottom
RV532  10K_0402_5%  [R_0402]  148.72 77.28 270 bottom
RV533  0_0805_5%  [R0805_0OHM]  154.8 81.97 0 top
RV534  100K_0402_5%  [R_0402]  151.06 75.56 0 top
RV535  1M_0402_5%  [R_0402]  66.89 21.83 180 top
RV536  100K_0402_5%  [R_0402]  62.8 29.96 0 top
RV537  100K_0402_5%  [R_0402]  62.8 30.98 0 top
RV538  0_0402_5%  [R0402_0OHM]  63.71 26.91 180 top
RV539  0_0402_5%  [R0402_0OHM]  55.24 37.25 0 bottom
RV540  0_0402_5%  [R0402_0OHM]  55.24 36.36 0 bottom
RV541  0_0402_5%  [R0402_0OHM]  55.24 39.03 0 bottom
RV542  0_0402_5%  [R0402_0OHM]  55.24 38.14 0 bottom
RV543  0_0402_5%  [R0402_0OHM]  55.24 40.8 0 bottom
RV544  0_0402_5%  [R0402_0OHM]  55.24 39.92 0 bottom
RV546  0_0402_5%  [R0402_0OHM]  55.24 42.71 0 bottom
RV548  0_0402_5%  [R0402_0OHM]  55.24 41.82 0 bottom
RV549  0_0402_5%  [R0402_0OHM]  55.24 34.58 0 bottom
RV551  100K_0402_5%  [R_0402]  62.8 31.87 0 top
RV552  0_0402_5%  [R0402_0OHM]  55.24 35.47 0 bottom
RV554  150_0402_5%  [R_0402]  293.94 65.01 0 top
RV557  150_0402_5%  [R_0402]  292.95 65.01 180 top
RV561  20K_0402_5%  [R_0402]  296.38 61.33 180 bottom
RV562  150_0402_5%  [R_0402]  296.89 75.94 180 top
RV565  150_0402_5%  [R_0402]  294.98 75.94 180 top
RV566  0_0402_5%  [R0402_0OHM]  63.71 28.95 180 top
RV567  100K_0402_5%  [R_0402]  62.77 25.95 0 top
RV570  100K_0402_5%  [R_0402]  65.97 22.72 0 top
RV571  0_0402_5%  [R_0402]  157.62 72.94 90 top
RV572  0_0402_5%  [R0402_0OHM]  145.22 73.4 0 bottom
RV573  10K_0402_5%  [R_0402]  156.73 72.94 90 top
RV578  10K_0402_5%  [R_0402]  152.84 75.5 90 top
RV579  10K_0402_5%  [R_0402]  147.38 82.03 0 bottom
RW3  300_0402_5%  [R_0402]  285.73 57.98 90 bottom
RW4  300_0402_5%  [R_0402]  207.02 32.43 90 top
RZ8  10_0402_1%  [R_0402]  203.9 75.3 0 top
RZ9  1_0402_5%  [R_0402]  153.87 107.31 180 top
RZ10  1_0402_5%  [R_0402]  155.88 75.83 0 top
RZ11  100_0402_5%  [R_0402]  155.24 79.82 0 top
RZ12  100K_0402_5%  [R_0402]  205.8 72.38 0 top
RZ13  0_1206_5%  [R1206_0OHM]  212.02 10.91 180 top
RZ26  0_0603_5%  [R0603_0OHM]  64.08 33.01 180 top
RZ32  100K_0402_5%  [R_0402]  140.41 15.41 90 top
RZ33  100K_0402_5%  [R_0402]  137.42 13.21 180 top
RZ34  0_0805_5%  [R0805_0OHM]  205.08 17.39 180 bottom
RZ37  0_0603_5%  [R0603_0OHM]  228.8 48.25 0 bottom
RZ38  100K_0402_5%  [R_0402]  207.2 47.28 90 bottom
RZ40  100K_0402_5%  [R_0402]  66.1 35.74 0 top
RZ41  33_0402_5%  [R_0402]  241.69 38.55 270 bottom
RZ42  33_0402_5%  [R_0402]  240.67 38.55 270 bottom
RZ48  0_0603_5%  [R0603_0OHM]  133.37 96.56 0 bottom
RZ66  0_0603_5%  [R0603_0OHM]  131.83 93.75 180 top
RZ67  0_0603_5%  [R0603_0OHM]  70.63 47.4 180 top
RZ69  0_0603_5%  [R0603_0OHM]  171.58 73.69 90 top
RZ71  100K_0402_5%  [R_0402]  185 22.6 180 top
RZ96  100K_0402_5%  [R_0402]  233.18 45.76 90 bottom
RZ98  0_0603_5%  [R0603_0OHM]  257.83 26.66 0 top
RZ102  100K_0402_5%  [R_0402]  150.38 16.13 270 top
SW5  SKRBAAE010_4P  [SW_SKRBAAE010_4P]  292.72 62.27 180 bottom
T1  PAD~D  [TPC12]  169.61 20.11 180 bottom
T2  PAD~D  [TPC12]  155.76 36.77 180 bottom
T3  PAD~D  [TPC12]  252.27 30.39 180 bottom
T4  PAD~D  [TPC12]  154.95 40.5 180 bottom
T8  PAD~D  [TPC12]  155.71 18.47 180 bottom
T17  PAD~D  [TPC12]  170.98 19.75 180 bottom
T20  PAD~D  [TPC12]  173.97 24.78 0 top
T91  PAD~D  [TPC12]  153.25 38.6 180 bottom
T92  PAD~D  [TPC12]  169.81 27.68 0 top
T94  PAD~D  [TPC12]  154.52 38.27 180 bottom
T95  PAD~D  [TPC12]  282.51 42.19 180 bottom
T97  PAD~D  [TPC12]  176.29 79.34 0 top
T98  PAD~D  [TPC12]  149.73 83.94 180 bottom
T99  PAD~D  [TPC12]  149.79 82.64 180 bottom
T100  PAD~D  [TPC12]  152.1 85.46 180 bottom
T101  PAD~D  [TPC12]  150.6 85.44 180 bottom
T120  PAD~D  [TPC12]  154.98 29.99 180 bottom
T182  PAD~D  [TPC12]  162.92 31.09 0 top
T944  PAD~D  [TPC12]  282.86 43.92 180 bottom
T4931  PAD  [TPC12]  218.49 22.91 0 top
T4934  PAD~D  [TPC12]  173.82 27.24 0 top
T4936  PAD~D  [TPC12]  270.7 39.51 90 top
T4937  PAD~D  [TPC12]  269.88 39.87 270 bottom
TL2  MHPC_NS892407  [MHPC_NS892407_24P]  303.4 83.63 180 bottom
UA1  -  [G9090-180T11U_SOT23-5]  289.8 35.93 180 top
UA2  ALC1302  [ALC1302_QFN32_5X5]  261.78 21.34 270 bottom
UC1  -  [74AUP1G07GW_TSSOP5]  84.64 83.11 270 bottom
UC16  -  [74AUP1G07GW_TSSOP5]  134.89 75.67 90 top
UE1  -  [MEC1404-NU-TR_VTQFP128_14X14]  220.22 30.14 0 top
UE4  -  [SY6288D20AAC_SOT23-5]  136.86 16.43 270 top
UE6  -  [SN74LVC1G06DCKR_SC70-5]  239.13 27.31 270 bottom
UH1  SKL-H_BGA1440  [SKL-H_BGA_1440P-T]  128.21 73.73 270 bottom
UH2  SKY-H-PCH_BGA837  [SKY-S-PCH_BGA_837P-T]  178.81 43.61 0 bottom
UH7  -  [MC74VHC1G08DFT2G_SC70-5]  166.11 15.93 0 bottom
UH8  -  [W25Q128FVSIQ_SO8]  181.89 11.55 270 bottom
UH14  -  [MC74VHC1G08DFT2G_SC70-5]  189.9 25.67 90 top
UL1  RTL8111H-CG_QFN32_4X4  [RTL8111H-CG_QFN32_4X4-S]  284.61 46.74 270 bottom
UL2  -  [SY6288C20AAC_SOT23-5]  280.61 50.6 270 bottom
UM1  PS175HDMBGA64GTR2-A0_TFBGA64  [PS175HDMBGA64GTR2-A0_TFBGA_64P]  262.89 32.24 90 top
UM2  -  [W25X20CLSNIG_SO8]  262.98 27.73 270 top
US1  TPS2544RTER_WQFN16_3X3  [TPS2544RTER_WQFN16_3X3-S]  281.14 36.5 270 top
US2  -  [SY6288D20AAC_SOT23-5]  291.23 30.34 0 top
UT1  -  [F75303M_MSOP10]  61.85 49.76 270 bottom
UV1  N15P-GT_BGA908  [N15P-GT_BGA_908P]  182.09 76.11 90 bottom
UV6  H5GC4H24MFR-T2C  [H5GQ1H24AFR-T2L_BGA_170P]  175.6 118.89 0 bottom
UV7  H5GC4H24MFR-T2C  [H5GQ1H24AFR-T2L_BGA_170P]  166.7 131.69 180 bottom
UV8  H5GC4H24MFR-T2C  [H5GQ1H24AFR-T2L_BGA_170P]  197.46 87.48 270 bottom
UV9  H5GC4H24MFR-T2C  [H5GQ1H24AFR-T2L_BGA_170P]  210.26 96.19 90 bottom
UV11  TC7SH08FU_SSOP5~D  [TC7SH08FU_SSOP5]  148.15 84.71 270 bottom
UV14  TC7SH08FU_SSOP5~D  [TC7SH08FU_SSOP5]  142.31 76.3 90 bottom
UV17  -  [AP2330W-7_SC59-3]  295.28 63.43 0 bottom
UV18  TC7SH08FU_SSOP5~D  [TC7SH08FU_SSOP5]  153.75 74.05 270 top
UZ1  -  [EM5209VF_DFN14_3X2]  215.51 11.74 90 top
UZ8  -  [SY6288C20AAC_SOT23-5]  67.51 39.54 180 top
UZ9  -  [TPS22961DNYR_WSON8]  132.64 98.96 90 bottom
UZ15  -  [TPS22961DNYR_WSON8]  132.1 98.68 180 top
UZ16  -  [APE8937GN2_DFN8_2X2]  74.21 47.28 90 top
UZ17  -  [APE8937GN2_DFN8_2X2]  167.3 73.77 270 top
UZ21  -  [MC74VHC1G08DFT2G_SC70-5]  187.9 21.69 90 top
UZ22  -  [APE8937GN2_DFN8_2X2]  258.19 30.3 180 top
UZ23  -  [MC74VHC1G08DFT2G_SC70-5]  66.7 29.26 180 top
Y1  32.768KHZ_9PF_X1A000141000200  [Y_X1A000141000200_2P]  223.38 37.07 180 top
YH1  32.768KHZ_X1A000141000300  [Y_CM31532768DZFT_2P]  176.27 16.37 180 bottom
YH2  24MHZ_12PF_X3G024000DC1H  [Y_X3G024000DC1H_4P]  185.9 45.67 270 bottom
YL2  25MHZ_10PF_7V25000014  [Y_7V25000014_4P]  280.51 45.67 270 bottom
YM1  27MHZ_10PF_5YEA27000102IF50Q3  [Y_5YEA27000102IF50Q3_4P]  266.12 41.43 0 top
YV1  27MHZ_10PF_7V27000050  [Y_7V27000011_4P]  176.7 71.63 0 bottom

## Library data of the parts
CA1 CA8 CA10 CA11 CA13 = C_0603: room: AUDIO_DC_DC
CA2-CA4 CA7 CA9 CA12 CA14 = C_0402: room: AUDIO_DC_DC
CA15-CA17 CA20 CA21 CA24 CA26 CA28-CA33 CA36-CA47 CA52 CA54 CA55 CA57 CD91-CD95 PC114 = C_0402: room: AUDIO
CA18 CA19 CA22 CA23 CA25 CA27 CA48-CA51 CA53 CA56 PC113 = C_0603: room: AUDIO
CA34 CA35 = C_0201: room: AUDIO
CA60-CA62 CA67 CE2 CE99-CE102 CE104 CH185 CI24 CL32 CL43 CL44 CM44 CN7 CS25-CS28 CV152-CV154 CV602 CV603 CZ102 CZ104-CZ106 PC324 PC1523 PC1800 PC1802 PC1804 = C_0402
CA63-CA66 CE103 CN6 CV51 PC1801 PC1803 = C_0603
CC4 CC298 CH45-CH48 CH50-CH53 CH70 CH80 CH82 CH173 CH176 CH179 CH180 CH183 CH184 CH186-CH192 CH200 CH203 = C_0402: room: PCH
CC5 CH197 CZ47 CZ49 CZ57 CZ86 CZ88 = C_0402: room: CPU
CC27 = C_0402: room: RTC
CD1-CD4 CD12 CD16 CD17 CD69 CD74-CD79 CD96 CH101 = C_0402: room: DIMMA
CD5-CD10 CD13-CD15 CD70-CD73 = C_0603: room: DIMMA
CD11 = C_X: room: DIMMA
CD19-CD22 CD29-CD32 CD34 CD35 CD80-CD83 CH100 = C_0402: room: DIMMB
CD23-CD28 CD84-CD90 = C_0603: room: DIMMB
CD33 = C_APXK2R5ARA331MF451: room: DIMMB
CD36 = C_0603: room: NGFF SSD
CD37-CD46 CD51 CD53 = C_0402: room: NGFF SSD
CE1 CE4 CE5 = C_0402: room: KB
CE6 = C_0603: room: KB
CE8 CE12 CE62-CE69 CE71-CE74 CE76-CE79 CE81 CE82 CE84-CE87 CE91 CE98 = C_0402: room: EC
CE9 CE10 CE80 CT79 = C_0402: room: TOUCH PAD
CE89 = C_0603: room: EC
CH5-CH36 = C_0201: room: CPU
CH102-CH104 CH111-CH132 CH136 = C_0603: room: CPU_DECAP
CH106 CH110 CH133-CH135 CH204 = C_0402: room: CPU_DECAP
CH177 CH178 CH181 CH182 CH201 CH202 = C_0603: room: PCH
CI9 CI10 CI13 = C_0402: room: USB2
CI11 = C_0805: room: USB2
CI12 = C_0603: room: USB2
CI16 CI19 CI20 CI23 = C_0402: room: USB1
CI17 = C_0805: room: USB1
CI18 = C_0603: room: USB1
CL15 CL19-CL22 CL24 CL30 CL31 CL34-CL37 CL39 CL42 = C_0402: room: LAN
CL33 = C_1206: room: LAN
CL41 = C_0402: room: FAN
CL47 CL48 = C_0402: signal model: C_0402_0.1U_0402_10V6K
CLRP1 = SHORTPADS: User Part Number: PART#; room: PCH
CM1 CM3-CM5 CM8 CM10-CM13 CM22 CM24-CM26 CM28-CM33 CM35-CM41 CM43 CV598-CV601 CZ98 CZ99 = C_0402: room: HDMI
CM2 CM9 CM23 CM27 CM34 CV597 = C_0603: room: HDMI
CM6 CM7 CM14-CM21 = C_0201: room: HDMI
CM45 CM46 = C_0201
CN1 = C_0603: room: NGFF WLAN
CN2 CN8 CN9 CN20 CN21 = C_0402: room: NGFF WLAN
CS12-CS14 = C_0402: room: HDD
CS15 = C_0603: room: HDD
CT80 CT82-CT85 = C_0402: room: THERMAL
CT81 = C_0201: room: THERMAL
CV50 CV73 CV83-CV86 CV96-CV99 CV123 CV151 CV156 = C_0805: room: VGA
CV52 CV53 CV70-CV72 CV87-CV90 CV100-CV109 CV112-CV114 CV117-CV119 CV121 CV155 CV202-CV212 CV214 CV215 CV568-CV571 CV573 CV574 CZ95 LV13 = C_0402: room: VGA
CV74-CV80 CV91-CV95 CV110 CV111 CV115 CV116 CV120 CV122 CV213 CV572 CV575 = C_0603: room: VGA
CV158 CV159 CV165-CV167 CV374-CV380 = C_0402: room: VRAM1
CV160-CV164 CV373 = C_0603: room: VRAM1
CV168-CV172 CV381 = C_0603: room: VRAM2
CV173-CV175 CV382-CV388 = C_0402: room: VRAM2
CV177 CV178 CV184-CV186 CV390-CV396 = C_0402: room: VRAM3
CV179-CV183 CV389 = C_0603: room: VRAM3
CV187-CV191 CV397 = C_0603: room: VRAM4
CV192-CV194 CV398-CV404 = C_0402: room: VRAM4
CV531-CV548 CV550-CV552 CV557-CV567 = C_0201: room: VGA
CV576 CV579-CV581 CV585-CV592 = C_0402: room: EDP
CV577 CV578 = C_0603: room: EDP
CV582 CV583 CZ43 CZ44 EC5205 EC5206 = C_0402: room: CAMERA
CV584 = C_0603: room: CAMERA
CZ4 CZ6 = C_0402: room: 3V_5V_DC_DC
CZ8 CZ9 CZ11 CZ12 = C_0603: room: 3V_5V_DC_DC
CZ28 CZ96 CZ97 = C_0402: room: CPU_DC_DC
CZ41 = C_0402: room: EDP_DC_DC
CZ107 = C_0805
D1 = BAT54C-7-F_SOT23-3: room: AUDIO
D2 = BAT54A-7-F_SOT23-3
DA1 = TVNST52302AB0_SOT523-3: room: AUDIO
DA2 DA3 = AZ5125-02SPR7G_SOT23-3: room: AUDIO
DA4 DA5 = AZ5125-02SPR7G_SOT23-3
DA6 = AZ5123-01F-R7GR_DFN1006P2X2
DC2 = BAT54CW-7-F_SOT323-3: room: RTC
DE4 = IP4223CZ6_SO6-6: room: TOUCH PAD
DE7 DE9 DV1 DV9 DV11 = RB751S40T1G_SOD523-2
DE8 = AZ5125-01HPR7G_SOD523-2: room: EC
DH1 = RB751S40T1G_SOD523-2: room: PCH
DI1 = RB751S40T1G_SOD523-2: room: EDP
DI3 = AZ5125-02SPR7G_SOT23-3: room: EDP
DI7 = AZ1045-04F_DFN2510P10E-10-9: room: USB2
DI8 = AZ5125-02SPR7G_SOT23-3: room: USB2
DI9 = AZ1045-04F_DFN2510P10E-10-9: room: USB1
DI10 = AZ5125-02SPR7G_SOT23-3: room: USB1
DN1 DN2 = RB751S40T1G_SOD523-2: room: NGFF WLAN
DV2 = BAT54CW-7-F_SOT323-3: room: EDP
DV3 = BAT54CW-7-F_SOT323-3: room: EDP_DC_DC
DV4 DV5 = AZ1045-04F_DFN2510P10E-10-9: room: HDMI
DV12 = PESD5V0U2BT_SOT23-3: room: CAMERA
DV13 = BAT54CW-7-F_SOT323-3
F1 = F_NANOSMDC050F-13P2-2: room: KB
FD1-FD4 = FIDUCIAL_C40M80
H1-H4 = H_3P7
H5 H6 = H_3P2: room: ETY-ROOM
H10-H12 H17 = H_2P8: room: ETY-ROOM
H13 H23 = H_2P5: room: ETY-ROOM
H19 = H_2P8
H20 = H_3P3: room: ETY-ROOM
H40 = H_2P1N: room: ETY-ROOM
H55 = H_2P4X2P1N: room: ETY-ROOM
H56 = H_2P5
H57 = H_3P0
HDA1 = ALC3246-CG_MQFN48_6X6-S: room: AUDIO
HT1 RT1 RT3-RT7 = R_0402: room: THERMAL
JADP10 = ACES_50290-00701-001_7P
JAPS = ACES_50506-01841-P01_18P: room: CPU
JBAT10 = ACES_50288-01171-001_11P-T
JBL1 = E-T_6913K-Y04N-00L_4P: room: KB
JCAM1 = ACES_87212-14G0_14P: room: CAMERA
JDEG1 JLPDE1 = ACES_50506-01041-P01_10P: room: EC
